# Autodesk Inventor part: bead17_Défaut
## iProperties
Shininess: 64.0
Length Units: 11269
Angle Units: 11279
Time Units: 11290
Mass Units: 11283
Length Display Precision: 3
Angle Display Precision: 2
Compacted: True
Part Number: bead17_Défaut
Document SubType Name: Modeling
Created: 2006-01
Material: Par défaut
Designer: Fricot
Density: 0.0
Volumn: 0.0
Area: 0.0
PropertySet Name: Model Information
Control State: 0
Master: False
Checked Out: False
Author: Fricot
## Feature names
1. Base1
